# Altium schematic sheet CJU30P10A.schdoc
size 127 x 101 mm
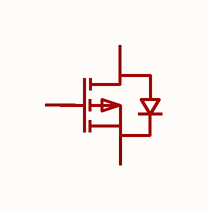
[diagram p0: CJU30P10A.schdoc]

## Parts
Q?  cju30p10a  [TO-252-2_L6.6-W6.1-P4.57-LS9.9-BR-CW]  (value not drawn)

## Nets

Not connected (* = marked no-connect by the designer): Q? 1(G) 2(D) 3(S)

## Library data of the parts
Q? = cju30p10a: 数量:1个P沟道;漏源电压(Vdss):100V;连续漏极电流(Id):30A;导通电阻(RDS(on)):52mΩ@4.5V;耗散功率(Pd):89W;阈值电压(Vgs(th)):1.5V;; Manufacturer: CJ(江苏长电/长晶); AddInBom: yes; ModelId: ce57f84d66384067af8a68020b6de06d; ModelName: TO-252-2L-3P_L6.6-W6.1-H2.3-LS10.1-P4.6; ModelTransform: 259.842,390.52442,0,90,0,0,-39.39,0,0; Number: 1个P沟道; Drain to Source Voltage: 100V; Current - Continuous Drain(Id): 30A; Pd - Power Dissipation: 89W; Gate Threshold Voltage (Vgs(th)): 1.5V; Input Capacitance(Ciss): 3.765nF; Reverse Transfer Capacitance (Crss@Vds): 136pF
